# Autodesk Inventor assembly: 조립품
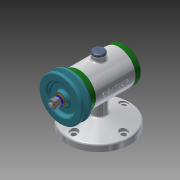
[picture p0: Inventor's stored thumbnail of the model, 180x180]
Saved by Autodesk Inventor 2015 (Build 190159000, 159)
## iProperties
Created: 2018-12
Part Number: 조립품
Document SubType Name: Assembly
Designer: now
Author: now
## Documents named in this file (15)
- C:\Users\now\Desktop\차지철\481207V1068\답안조립품.iam
- C:\Users\now\Desktop\차지철\481207V1068\V벨트풀리.ipt
- C:\Users\now\Desktop\차지철\481207V1068\고무캡.ipt
- C:\Users\now\Desktop\차지철\481207V1068\너트 M8.ipt
- 너트 M8.ipt
- C:\Users\now\Desktop\차지철\481207V1068\뒤커버.ipt
- C:\Users\now\Desktop\차지철\481207V1068\베어링 15 x 32 x 9.ipt
- C:\Users\now\Desktop\차지철\481207V1068\본체.ipt
- C:\Users\now\Desktop\차지철\481207V1068\볼트 M4 x 12.ipt
- C:\Users\now\Desktop\차지철\481207V1068\스프링와셔 8.ipt
- C:\Users\now\Desktop\차지철\481207V1068\앞커버.ipt
- C:\Users\now\Desktop\차지철\481207V1068\오일 실 15 25 7.ipt
- C:\Users\now\Desktop\차지철\481207V1068\와셔 8x17.ipt
- C:\Users\now\Desktop\차지철\481207V1068\축.ipt
- C:\Users\now\Desktop\차지철\481207V1068\키 3 x 3 x 12.ipt
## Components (2 placed, 2 different names)
1. V벨트풀리:1 — 각도:2
2. 고무캡:1
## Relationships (1: Angle 1)
- 각도:2 [Angle]: V벨트풀리:1
